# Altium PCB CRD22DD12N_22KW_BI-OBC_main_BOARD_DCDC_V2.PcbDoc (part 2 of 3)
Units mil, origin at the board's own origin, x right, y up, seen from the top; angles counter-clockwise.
Board outline 9308.07 x 7086.6 mil, 4 copper layers (TOP, GND02, POWER03, BOTTOM), stack 74.3 mil thick; 339 components, 177 nets, 874 pads, 199 vias.
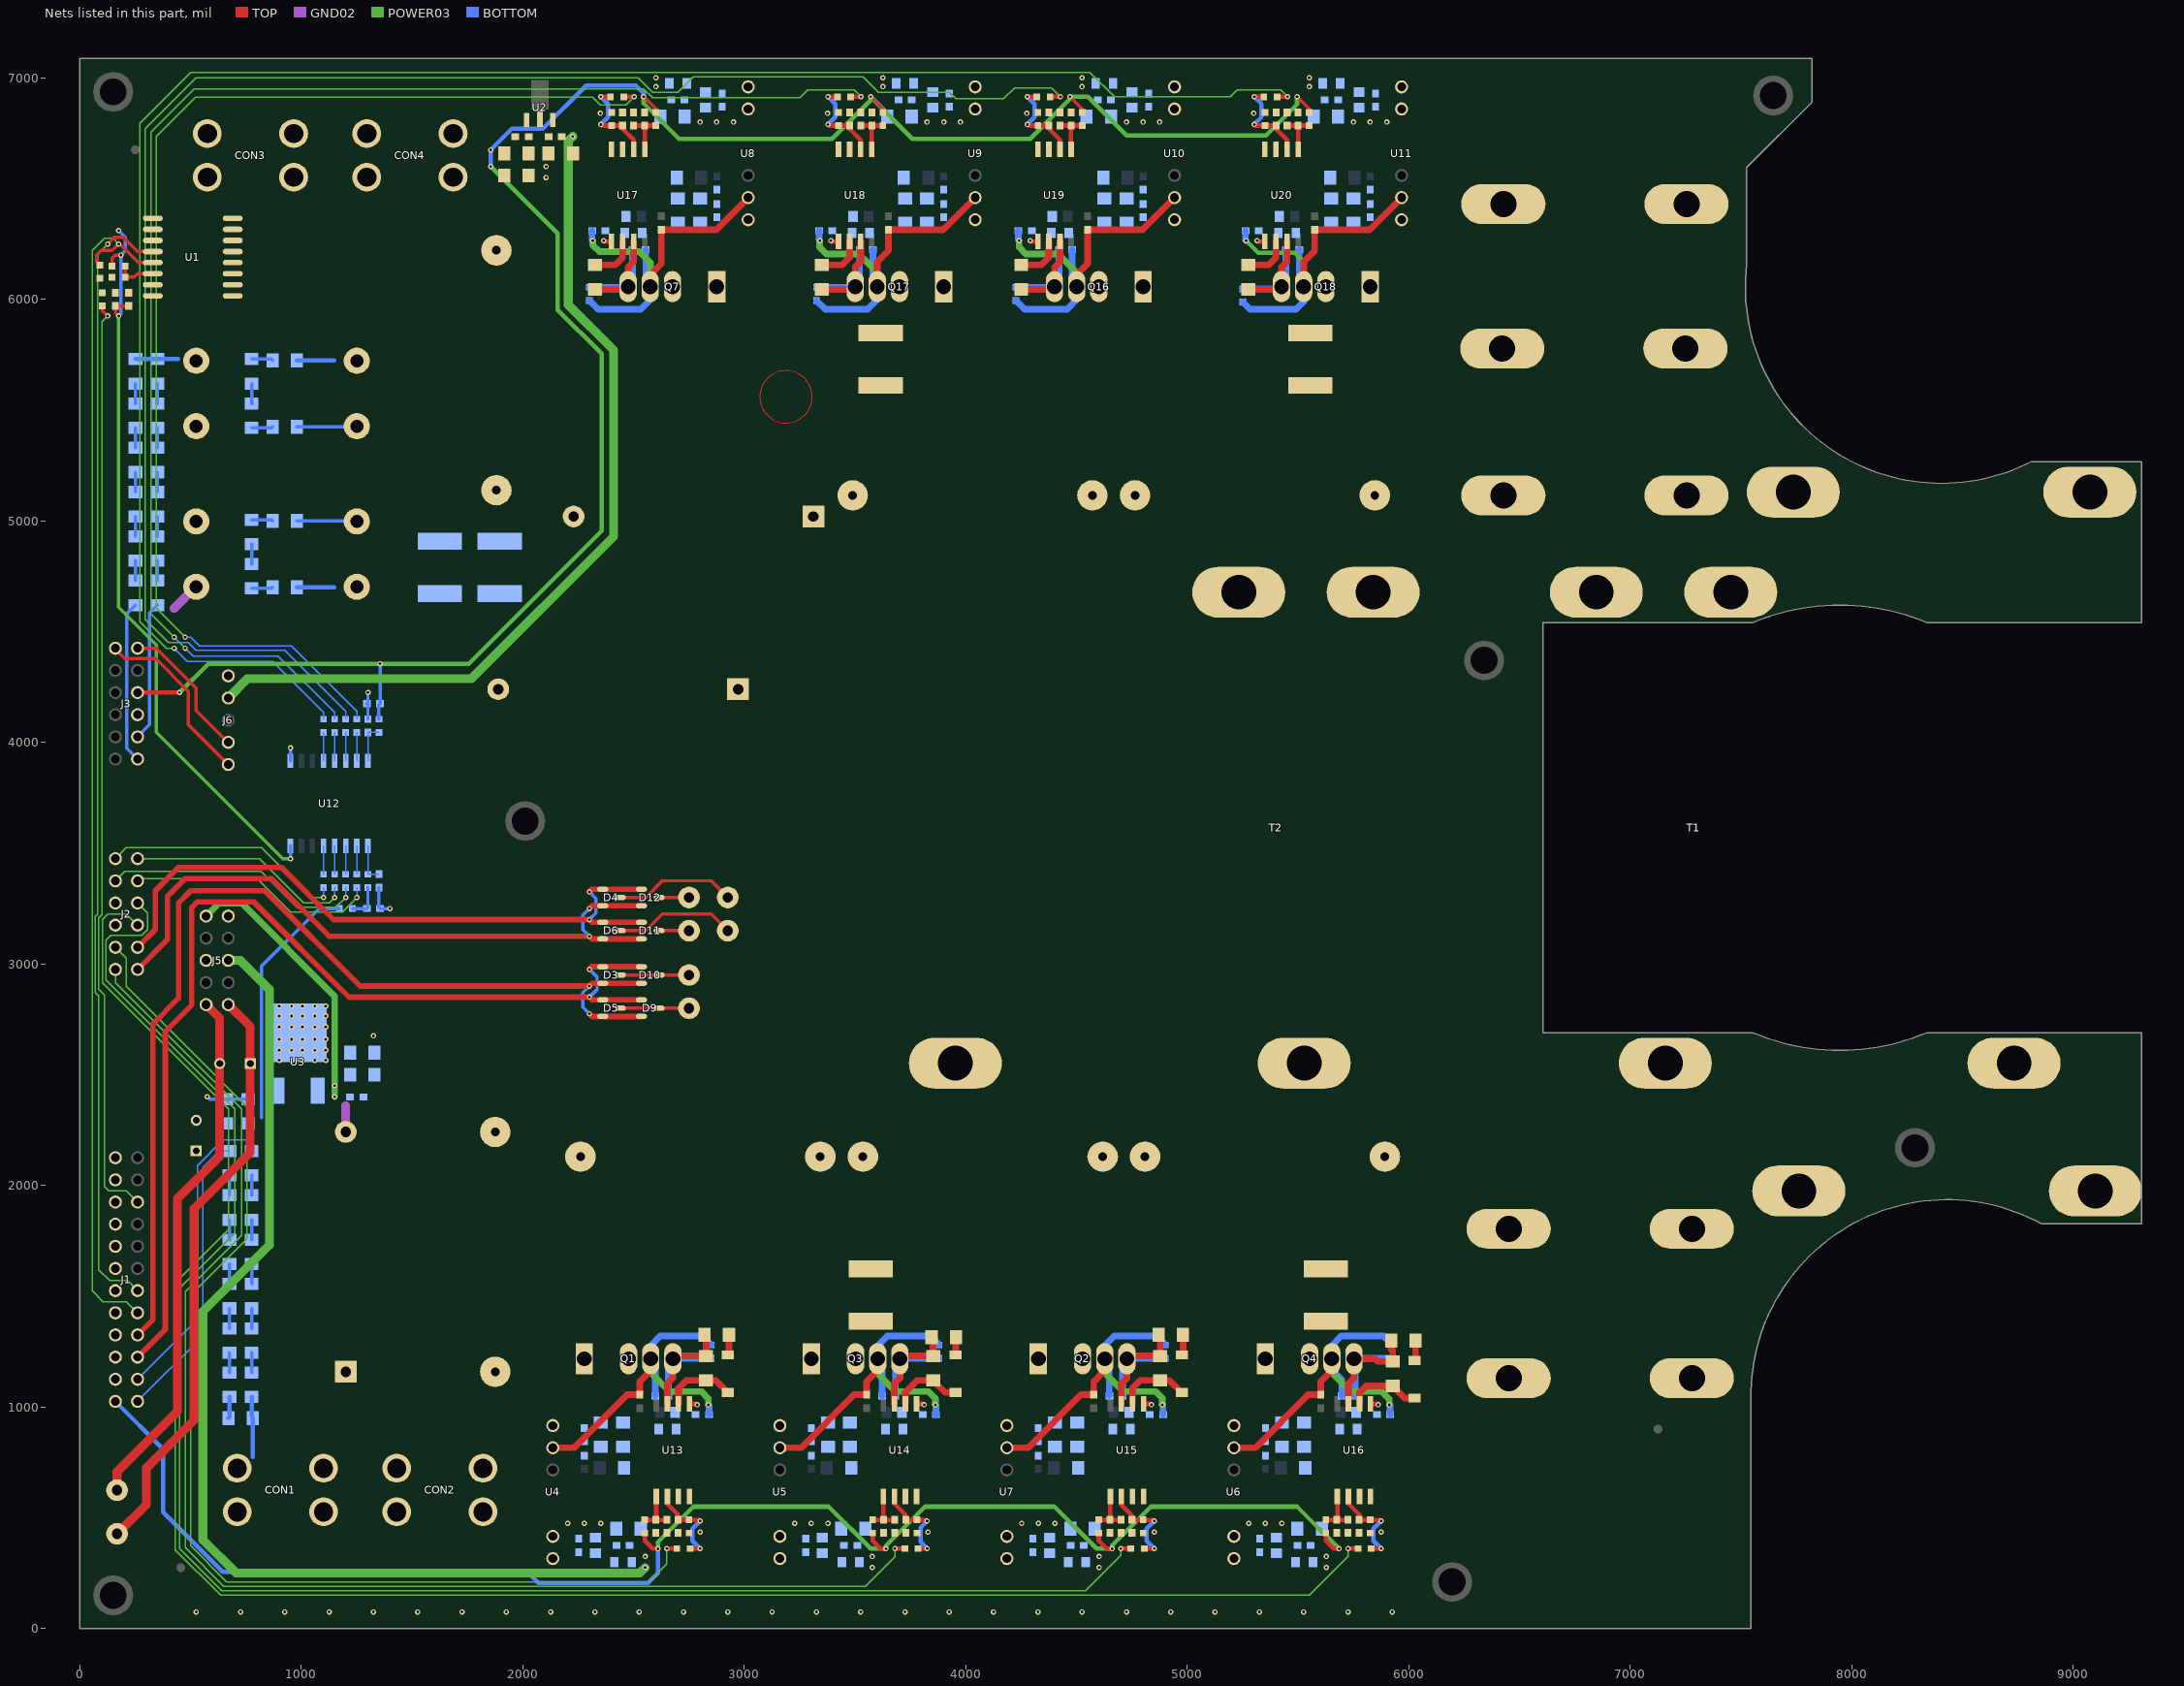
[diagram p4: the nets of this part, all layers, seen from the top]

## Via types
v1: diameter 24, hole 12, TOP to BOTTOM, tented both sides, 199 vias

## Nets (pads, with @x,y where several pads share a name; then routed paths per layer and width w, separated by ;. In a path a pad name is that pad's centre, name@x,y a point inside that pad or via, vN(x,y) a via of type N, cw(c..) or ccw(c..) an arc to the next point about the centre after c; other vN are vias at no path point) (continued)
AGND: C20.2 C21.2 C49.1 C50.1 C51.1 C52.1 C53.1 C54.2 C66.2 C67.2 C70.2 C71.2 C73.2 C74.2 C75.2 C76.2 C77.2 C78.2 C79.2 C80.2 C81.2 C82.2 C83.2 C84.2 C130.2 C131.1 C134.2 C135.2 C136.2 C141.2 C142.2 C143.2 C148.2 C149.2 C150.2 C155.2 C156.2 C157.2 J1.13 J1.15 J1.17 J1.19 J1.21 J2.6 J2.8 J5.6 J5.9 R45.2 R105.2 R110.2 R114.2 R117.2 U1.9 U1.10 U1.11 U3.2 U4.2 U5.2 U6.2 U7.2 U12.8 U13.3 U13.4 U14.3 U14.4 U15.3 U15.4 U16.3 U16.4 | length 3901.4
  TOP w15: R45.2@145.08,6150 145.08,6185.08 160,6200 v1(185,6200) ; v1(175,5925) 160,5940 C21.2@160,5970.08 C20.2@220,5970.08
  GND02 w40: 1200,2241.34 1200,2360
  POWER03 w15: v1(175,5925) 175,4610 345,4440 345,4045 915,3475 v1(950,3475)
  BOTTOM w15: v1(175,5925) 185,5935 v1(185,6200) 205,6220 205,6280 v1(175,6310) ; v1(575,2400) 585.63,2389.37 C53.1@659.25,2389.37 C52.1@759.25,2389.37 ; v1(950,3475) U12.8@950,3533 ; C131.1@1350,3345.08 1350,3254.92 C130.2@1354.92,3250 v1(1400,3250)
  other v1: 525,75 725,75 925,75 1125,75 1325,75 1525,75 1725,75 1925,75 2125,75 2325,75 2525,75 2725,75 2925,75 3125,75 3325,75 3525,75 3725,75 3925,75 4125,75 4325,75 4525,75 4725,75 4925,75 5125,75 5325,75 5525,75 5725,75 5925,75 2800,435.68 3829.17,435.68 4850,435.68 5875,435.68 2202,475 2277,475 2352,475 3227,475 3302,475 3377,475 4252,475 4327,475 4402,475 5277,475 5352,475 5427,475 900,2565 955,2565 1005,2565 1060,2565 1110,2565 900,2610 955,2610 1005,2610 1060,2610 1110,2610 900,2660 955,2660 1005,2660 1060,2660 1110,2660 1325,2675 900,2715 955,2715 1005,2715 1060,2715 1110,2715 900,2765 955,2765 1005,2765 1060,2765 1110,2765 900,2810 955,2810 1005,2810 1060,2810 1110,2810
CAN5V_GND: J3.11 J6.2 | length 644.2
  TOP w15: J3.11@260,4425 345,4425 525,4245 525,4144.77 J6.2@669.52,4000.24
CAN_5V: J3.12 J6.1 | length 817.8
  TOP w15: J3.12@160,4425 160,4420 202,4378 342,4378 490,4230 490,4079.76 J6.1@669.52,3900.24
CLAMPQA: C5.1 Q1.4 R2.1 R4.1 R8.2 U13.7 | length 817.1
  TOP w30: U13.7@2652,1014 2652,1105 2677,1130 Q1.4@2677,1217.72 2689.4,1230.12 R4.1@2827,1230.12 2827,1317.88 R2.1@2819.88,1325
  BOTTOM w30: C5.1@2656.92,1050 2656.92,1197.64 Q1.4@2677,1217.72 2679.36,1220.08 R8.2@2850,1220.08
CLAMPQB: C14.1 Q3.4 R15.1 R19.1 R21.2 U14.7 | length 811.2
  TOP w30: U14.7@3677,1014 3677,1105 3702,1130 Q3.4@3702,1217.72 3714.4,1230.12 R19.1@3852,1230.12 3852,1307.88 R15.1@3844.88,1315
  BOTTOM w30: C14.1@3681.92,1050 3681.92,1197.64 Q3.4@3702,1217.72 3704.36,1220.08 R21.2@3879.17,1220.08
CLAMPQC: C4.1 Q2.4 R1.2 R5.2 R9.2 U15.7 | length 817.1
  TOP w30: U15.7@4702,1014 4702,1105 4727,1130 Q2.4@4727,1217.72 4739.4,1230.12 R5.2@4877,1230.12 4877,1317.88 R1.2@4869.88,1325
  BOTTOM w30: C4.1@4706.92,1050 4706.92,1197.64 Q2.4@4727,1217.72 4729.36,1220.08 R9.2@4900,1220.08
CLAMPQD: C15.1 Q4.4 R14.2 R20.2 R22.2 U16.7 | length 835.9
  TOP w30: U16.7@5727,1014 5727,1105 5752,1130 Q4.4@5752,1217.72 5847.28,1217.72 5859.88,1205.12 R20.2@5927,1205.12 5927,1253 5919.88,1260.12 R14.2@5919.88,1300
  BOTTOM w30: C15.1@5756.92,1050 5756.92,1212.8 Q4.4@5752,1217.72 5754.36,1220.08 R22.2@5925,1220.08
CLAMPQSA: C22.1 Q7.4 R58.1 R62.2 U17.7 | length 721.2
  TOP w30: R58.1@2325,6044.88 2462.6,6044.88 Q7.4@2475,6057.28 2475,6145 2500,6170 U17.7@2500,6261
  BOTTOM w30: R62.2@2300,6054.92 2472.64,6054.92 Q7.4@2475,6057.28 2495.08,6077.36 C22.1@2495.08,6225
CLAMPQSB: C42.1 Q17.4 R72.1 R75.2 U18.7 | length 721.2
  TOP w30: R72.1@3350,6044.88 3487.6,6044.88 Q17.4@3500,6057.28 3500,6145 3525,6170 U18.7@3525,6261
  BOTTOM w30: R75.2@3325,6054.92 3497.64,6054.92 Q17.4@3500,6057.28 3520.08,6077.36 C42.1@3520.08,6225
CLAMPQSC: C23.1 Q16.4 R59.2 R64.2 U19.7 | length 721.2
  TOP w30: R59.2@4250,6044.88 4387.6,6044.88 Q16.4@4400,6057.28 4400,6145 4425,6170 U19.7@4425,6261
  BOTTOM w30: R64.2@4225,6054.92 4397.64,6054.92 Q16.4@4400,6057.28 4420.08,6077.36 C23.1@4420.08,6225
CLAMPQSD: C43.1 Q18.4 R73.2 R76.2 U20.7 | length 724.2
  TOP w30: R73.2@5275,6044.88 5412.6,6044.88 Q18.4@5425,6057.28 5425,6145 5450,6170 U20.7@5450,6261
  BOTTOM w30: R76.2@5250,6047.64 5415.35,6047.64 Q18.4@5425,6057.28 5445.08,6077.36 C43.1@5445.08,6225
CS: D4.2 D6.2 D11.2 D12.2 J2.1 | length 3062.4
  TOP w25: J2.1@260,2975 395,3110 395,3305 475,3385 865,3385 1125,3125 v1(2300,3125) 2312.4,3112.6 D6.2@2360.24,3112.6 D11.2@2535.24,3112.6 ; v1(2300,3250) 2312.6,3262.6 D4.2@2360.24,3262.6 D12.2@2535.24,3262.6
  BOTTOM w15: v1(2300,3125) 2270,3155 2270,3220 v1(2300,3250)
CS_PRI: D3.2 D5.2 D9.2 D10.2 J1.18 | length 4713.2
  TOP w25: J1.18@260,1325 330,1395 330,2730 445,2845 445,3275 500,3330 835,3330 1265,2900 v1(2300,2900) 2312.6,2912.6 D3.2@2360.24,2912.6 D10.2@2535.24,2912.6 ; v1(2300,2775) 2312.4,2762.6 D5.2@2360.24,2762.6 D9.2@2535.24,2762.6
  BOTTOM w15: v1(2300,2775) 2270,2805 2270,2870 v1(2300,2900)
CS_RTN: D4.1 D6.1 D11.1 D12.1 J2.3 | length 3019.7
  TOP w25: J2.3@260,3075 340,3155 340,3330 445,3435 910,3435 1145,3200 v1(2300,3200) 2312.6,3187.4 D6.1@2360.24,3187.4 D11.1@2535.24,3187.4 ; v1(2300,3325) 2312.4,3337.4 D4.1@2360.24,3337.4 D12.1@2535.24,3337.4
  BOTTOM w15: v1(2300,3200) 2330,3230 2330,3295 v1(2300,3325)
CS_RTN_PRI: D3.1 D5.1 D9.1 D10.1 J1.20 | length 4749.8
  TOP w25: J1.20@260,1225 385,1350 385,2695 505,2815 505,3255 530,3280 785,3280 1215,2850 v1(2300,2850) 2312.6,2837.4 D5.1@2360.24,2837.4 D9.1@2535.24,2837.4 ; v1(2300,2975) 2312.4,2987.4 D3.1@2360.24,2987.4 D10.1@2535.24,2987.4
  BOTTOM w15: v1(2300,2850) 2335,2885 2335,2940 v1(2300,2975)
DC-OV: J1.22 R70.1 | length 1410.6
  BOTTOM w6: J1.22@260,1125 530.25,1395.25 530.25,2090.25 645,2205 760,2205 775,2190 R70.1@775,2155.12
DC_14V_INPUT: C55.1 J4.2 J5.1 | length 2679
  TOP w40: J4.2@167.72,427.36 300.16,559.8 300.16,725.16 515,940 515,1895 768.9,2148.9 C55.1@768.9,2550 768.9,2716.76 J5.1@669.52,2816.14
DC_FB: J1.24 R69.1 | length 1328.3
  BOTTOM w6: J1.24@260,1025 555,1320 555,2080 630.12,2155.12 R69.1@675,2155.12
DCINPUT: C1.1 C2.1 C7.1 C8.1 C10.1 C185.1 C633.1 CON1.1 CON1.2 CON1.3 CON1.4 Q1.1 Q2.1 R34.2 R42.2 | length 272.1
  BOTTOM w6: 780,775 780.12,775.12
  BOTTOM w20: R42.2@775,1044.88 775,955.12 R34.2@780.12,950 780.12,775.12
DCPWM1A_1H: J2.4 R104.1 | length 5420.6
  TOP w20: v1(2650,360.68) R104.1@2695.08,360.68
  POWER03 w6: J2.4@160,3075 210,3025 210,2900 755,2355 755,1760 500,1505 500,372.78 662.78,210 2570,210 2650,290 v1(2650,360.68)
DCPWM1A_1L: J2.2 R108.1 | length 6364.2
  TOP w20: v1(3679.17,360.68) R108.1@3724.25,360.68
  POWER03 w6: J2.2@160,2975 160,2915 730,2345 730,1775 475,1520 475,365.91 649.91,191 3546,191 3679.17,324.17 v1(3679.17,360.68)
DCPWM2A_2H: J2.7 R112.1 | length 7908.9
  TOP w20: v1(4700,360.68) R112.1@4745.08,360.68
  POWER03 w6: J2.7@260,3275 305,3230 305,3155 280,3130 140,3130 117.5,3107.5 117.5,2927.5 700,2345 700,1785 450,1535 450,360 640,170 4540,170 4700,330 v1(4700,360.68)
DCPWM2A_2L: J2.5 R116.1 | length 8903.9
  TOP w20: v1(5725,360.68) R116.1@5770.08,360.68
  POWER03 w6: J2.5@260,3175 210,3225 125,3225 101,3201 101,2914 670,2345 670,1800 430,1560 430,355 635,150 5550,150 5725,325 v1(5725,360.68)
DRVA: D1.2 R4.2 U13.6 | length 331
  TOP w30: U13.6@2702,1014 2702,1085 2736.88,1119.88 R4.2@2827,1119.88 2870.47,1119.88 D1.2@2925,1065.35
DRVA_G: C5.2 C56.2 C57.2 C58.2 C85.1 C86.1 C138.2 C139.1 Q1.3 R8.1 U4.6 | length 1663.8
  TOP w30: U4.6@2135.07,815.75 2230.75,815.75 2469.92,1054.92 C139.1@2527,1054.92 2527,1115 2577,1165 Q1.3@2577,1217.72
  POWER03 w30: Q1.3@2577,1217.72 2577,1153 2660,1070 2805,1070 2837,1038 v1(2837,1010)
  BOTTOM w30: C5.2@2597.08,1050 2597.08,1197.64 Q1.3@2577,1217.72 2577,1277 2620,1320 2809.92,1320 R8.1@2850,1279.92 ; v1(2837,1010) 2839.92,1007.08 C138.2@2839.92,965
DRVB: D7.2 R19.2 U14.6 | length 324.7
  TOP w30: U14.6@3727,1014 3727,1067 3779.88,1119.88 R19.2@3852,1119.88 3906.53,1065.35 D7.2@3954.17,1065.35
DRVB_G: C14.2 C59.2 C60.2 C68.2 C89.1 C91.1 C144.2 C146.1 Q3.3 R21.1 U5.6 | length 1670.4
  TOP w30: U5.6@3160.07,815.75 3255.75,815.75 3494.92,1054.92 C146.1@3552,1054.92 3552,1115 3602,1165 Q3.3@3602,1217.72
  POWER03 w30: Q3.3@3602,1217.72 3602,1148.83 3680.83,1070 3830,1070 3862,1038 v1(3862,1010)
  BOTTOM w30: C14.2@3622.08,1050 3622.08,1197.64 Q3.3@3602,1217.72 3602,1277 3645,1320 3839.09,1320 R21.1@3879.17,1279.92 ; v1(3862,1010) 3864.92,1007.08 C144.2@3864.92,965
DRVC: D2.2 R5.1 U15.6 | length 331
  TOP w30: U15.6@4752,1014 4752,1085 4786.88,1119.88 R5.1@4877,1119.88 4920.47,1119.88 D2.2@4975,1065.35
DRVC_G: C4.2 C61.2 C62.2 C69.2 C87.1 C88.1 C152.2 C153.1 Q2.3 R9.1 U7.6 | length 1665
  TOP w30: U7.6@4185.07,815.75 4280.75,815.75 4519.92,1054.92 C153.1@4577,1054.92 4577,1115 4627,1165 Q2.3@4627,1217.72
  POWER03 w30: Q2.3@4627,1217.72 4627,1153 4710,1070 4857,1070 4887,1040 v1(4887,1010)
  BOTTOM w30: C4.2@4647.08,1050 4647.08,1197.64 Q2.3@4627,1217.72 4627,1277 4670,1320 4859.92,1320 R9.1@4900,1279.92 ; v1(4887,1010) 4889.92,1007.08 C152.2@4889.92,965
DRVD: D8.2 R20.1 U16.6 | length 333.9
  TOP w30: U16.6@5777,1014 5777,1064.88 5807,1094.88 R20.1@5927,1094.88 5981.53,1040.35 D8.2@6025,1040.35
DRVD_G: C15.2 C64.2 C65.2 C72.2 C90.1 C92.1 C158.2 C160.1 Q4.3 R22.1 U6.6 | length 1671.2
  TOP w30: U6.6@5210.07,815.75 5305.75,815.75 5544.92,1054.92 C160.1@5602,1054.92 5602,1115 5652,1165 Q4.3@5652,1217.72
  POWER03 w30: Q4.3@5652,1217.72 5652,1153 5735,1070 5875,1070 5912,1033 v1(5912,1010)
  BOTTOM w30: C15.2@5697.08,1050 5697.08,1122.92 5652,1168 Q4.3@5652,1217.72 5652,1277 5695,1320 5884.92,1320 R22.1@5925,1279.92 ; v1(5912,1010) 5914.92,1007.08 C158.2@5914.92,965
DRVSA: R58.2 U17.6 | length 210.4
  TOP w30: R58.2@2325,6155.12 2415.12,6155.12 2450,6190 U17.6@2450,6261
DRVSB: R72.2 U18.6 | length 210.4
  TOP w30: R72.2@3350,6155.12 3440.12,6155.12 3475,6190 U18.6@3475,6261
DRVSC: R59.1 U19.6 | length 210.4
  TOP w30: R59.1@4250,6155.12 4340.12,6155.12 4375,6190 U19.6@4375,6261
DRVSD: R73.1 U20.6 | length 210.4
  TOP w30: R73.1@5275,6155.12 5365.12,6155.12 5400,6190 U20.6@5400,6261
IGND: C55.2 J4.1 J5.2 | length 2409.4
  TOP w40: J4.1@167.72,624.22 167.72,707.72 440,980 440,1940 631.1,2131.1 C55.2@631.1,2550 631.1,2754.57 J5.2@569.52,2816.14
IOUT_ADC: J1.14 U1.12 | length 5117.2
  TOP w15: v1(125,6250) 155,6280 195,6280 259.25,6215.75 U1.12@329.01,6215.75
  POWER03 w6: v1(125,6250) 80,6205 80,3225.26 69,3214.26 69,2871 85,2855 85,1620 135,1570 215,1570 J1.14@260,1525
LEGA: Q1.2 Q3.1 T2.1
LEGB: CR1.2 CR2.2 Q2.2 Q4.1
N16123922: CON3.1 CON3.2 CON3.3 CON3.4 U1.5 U1.6 U1.7 U1.8
N16148248: R63.2 R67.1 | length 97
  BOTTOM w15: R67.1@775,5730.12 864.76,5730.12 R63.2@869.88,5725
N16148534: R68.2 R71.1 | length 97
  BOTTOM w15: R68.2@775,5419.88 864.76,5419.88 R71.1@869.88,5425
N16148538: R67.2 R68.1 | length 89.8
  BOTTOM w15: R68.1@775,5530.12 R67.2@775,5619.88
N16148540: R74.2 R77.1 | length 97
  BOTTOM w15: R77.1@775,5005.12 864.76,5005.12 R74.2@869.88,5000
N16148544: R78.2 R79.1 | length 97
  BOTTOM w15: R78.2@775,4694.88 864.76,4694.88 R79.1@869.88,4700
N16148550: C25.2 C26.2 C39.1 C40.1 R71.2 R74.1 | length 541.7
  BOTTOM w15: R74.1@980.12,5000 1247.64,5000 C39.1@1250,4997.64 ; R71.2@980.12,5425 1247.64,5425 C25.2@1250,5427.36
N16320789: R77.2 R78.1 | length 89.8
  BOTTOM w15: R78.1@775,4805.12 R77.2@775,4894.88
N17266948: R37.2 R44.1 | length 89.8
  BOTTOM w15: R44.1@350,5530.12 R37.2@350,5619.88
N17266951: R44.2 R49.1 | length 89.8
  BOTTOM w15: R49.1@350,5330.12 R44.2@350,5419.88
N17453412: C109.1 C110.1 R89.1 U9.1
N17453587: C98.1 C103.1 R88.1 U8.1
N17454238: C73.1 C74.1 R84.1 U4.1
N17454469: C71.1 C75.1 R85.1 U5.1
N17785545: C134.1 C135.1 R103.2 U13.1 | length 206.9
  TOP w20: R103.2@2550,490.6 C135.1@2600,490.6 ; U13.1@2602,596.68 2602,492.6 C135.1@2600,490.6 ; C134.1@2650,490.6 C135.1@2600,490.6
N17785579: C136.1 R104.2 R105.1 U13.2 | length 427.1
  TOP w20: U13.2@2652,596.68 2652,563 2700,515 C136.1@2700,490.6 R105.1@2750,490.6 2795.08,490.6 v1(2800,485.68) ; R104.2@2754.92,360.68 v1(2800,360.68)
  BOTTOM w20: v1(2800,360.68) 2765,395.68 2765,450.68 v1(2800,485.68)
N17785699: C141.1 C142.1 R107.2 U14.1 | length 207
  TOP w20: R107.2@3579.17,490.6 C141.1@3629.17,490.6 ; U14.1@3627,596.68 3627,492.77 C141.1@3629.17,490.6 ; C142.1@3679.17,490.6 C141.1@3629.17,490.6
N17785727: C143.1 R108.2 R110.1 U14.2 | length 416.3
  TOP w20: U14.2@3677,596.68 3677,563 3725,515 3725,494.77 C143.1@3729.17,490.6 R110.1@3779.17,490.6 3820.08,490.6 v1(3825,485.68) ; R108.2@3784.09,360.68 v1(3825,360.68)
  BOTTOM w20: v1(3825,360.68) 3795,390.68 3795,455.68 v1(3825,485.68)
N17785767: C137.1 C138.1 R106.1 U13.5 | length 36.7
  TOP w20: U13.5@2752,1014 2783,1014 v1(2787,1010)
N17785926: C144.1 C145.1 R109.1 U14.5 | length 36.7
  TOP w20: U14.5@3777,1014 3808,1014 v1(3812,1010)
N17788175: C148.1 C149.1 R111.2 U15.1 | length 206.9
  TOP w20: R111.2@4600,490.6 C149.1@4650,490.6 ; U15.1@4652,596.68 4652,492.6 C149.1@4650,490.6 ; C148.1@4700,490.6 C149.1@4650,490.6
N17788213: C150.1 R112.2 R114.1 U15.2 | length 427.1
  TOP w20: U15.2@4702,596.68 4702,558 4750,510 C150.1@4750,490.6 R114.1@4800,490.6 4845.08,490.6 v1(4850,485.68) ; R112.2@4804.92,360.68 v1(4850,360.68)
  BOTTOM w20: v1(4850,360.68) 4815,395.68 4815,450.68 v1(4850,485.68)
N17788281: C155.1 C156.1 R115.2 U16.1 | length 206.9
  TOP w20: R115.2@5625,490.6 C156.1@5675,490.6 ; U16.1@5677,596.68 5677,492.6 C156.1@5675,490.6 ; C155.1@5725,490.6 C156.1@5675,490.6
N17788301: C157.1 R116.2 R117.1 U16.2 | length 427.1
  TOP w20: U16.2@5727,596.68 5727,563 5775,515 C157.1@5775,490.6 R117.1@5825,490.6 5870.08,490.6 v1(5875,485.68) ; R116.2@5829.92,360.68 v1(5875,360.68)
  BOTTOM w20: v1(5875,360.68) 5840,395.68 5840,450.68 v1(5875,485.68)
N17788345: C151.1 C152.1 R113.1 U15.5 | length 36.7
  TOP w20: U15.5@4802,1014 4833,1014 v1(4837,1010)
N17788478: C158.1 C159.1 R118.1 U16.5 | length 36.7
  TOP w20: U16.5@5827,1014 5858,1014 v1(5862,1010)
N17790300: C161.1 C162.1 R119.2 U17.1 | length 206.1
  TOP w20: C161.1@2500,6784.4 C162.1@2550,6784.4 ; U17.1@2550,6678.32 C162.1@2550,6784.4 ; R119.2@2600,6784.4 C162.1@2550,6784.4
N17790352: C163.1 R120.2 R122.1 U17.2 | length 422.2
  TOP w20: v1(2352,6789.32) 2356.92,6784.4 R122.1@2400,6784.4 C163.1@2450,6784.4 2450,6769.32 2500,6719.32 U17.2@2500,6678.32 ; v1(2352,6914.32) R120.2@2395.08,6914.32
  BOTTOM w20: v1(2352,6789.32) 2385,6822.32 2385,6881.32 v1(2352,6914.32)
N17790406: C167.1 C168.1 R123.2 U18.1 | length 206.1
  TOP w20: C168.1@3525,6784.4 C167.1@3575,6784.4 ; U18.1@3575,6678.32 C167.1@3575,6784.4 ; R123.2@3625,6784.4 C167.1@3575,6784.4
N17790440: C169.1 R124.2 R125.1 U18.2 | length 422.2
  TOP w20: v1(3377,6789.32) 3381.92,6784.4 R125.1@3425,6784.4 C169.1@3475,6784.4 3475,6769.32 3525,6719.32 U18.2@3525,6678.32 ; v1(3377,6914.32) R124.2@3420.08,6914.32
  BOTTOM w20: v1(3377,6789.32) 3410,6822.32 3410,6881.32 v1(3377,6914.32)
N17790484: C164.1 C165.1 R121.1 U17.5 | length 36.7
  TOP w20: v1(2365,6265) 2369,6261 U17.5@2400,6261
N17790617: C170.1 C171.1 R126.1 U18.5 | length 36.7
  TOP w20: v1(3390,6265) 3394,6261 U18.5@3425,6261
N17792648: C173.1 C174.1 R127.2 U19.1 | length 206.1
  TOP w20: C174.1@4425,6784.4 C173.1@4475,6784.4 ; U19.1@4475,6678.32 C173.1@4475,6784.4 ; R127.2@4525,6784.4 C173.1@4475,6784.4
N17792696: C175.1 R128.2 R130.1 U19.2 | length 422.2
  TOP w20: v1(4277,6789.32) 4281.92,6784.4 R130.1@4325,6784.4 C175.1@4375,6784.4 4375,6769.32 4425,6719.32 U19.2@4425,6678.32 ; v1(4277,6914.32) R128.2@4320.08,6914.32
  BOTTOM w20: v1(4277,6789.32) 4310,6822.32 4310,6881.32 v1(4277,6914.32)
N17792742: C179.1 C180.1 R131.2 U20.1 | length 206.1
  TOP w20: C179.1@5450,6784.4 C180.1@5500,6784.4 ; U20.1@5500,6678.32 C180.1@5500,6784.4 ; R131.2@5550,6784.4 C180.1@5500,6784.4
N17792776: C181.1 R132.2 R133.1 U20.2 | length 422.2
  TOP w20: v1(5302,6789.32) 5306.92,6784.4 R133.1@5350,6784.4 C181.1@5400,6784.4 5400,6769.32 5450,6719.32 U20.2@5450,6678.32 ; v1(5302,6914.32) R132.2@5345.08,6914.32
  BOTTOM w20: v1(5302,6789.32) 5335,6822.32 5335,6881.32 v1(5302,6914.32)
N17792812: C176.1 C177.1 R129.1 U19.5 | length 36.7
  TOP w20: v1(4290,6265) 4294,6261 U19.5@4325,6261
N17792937: C182.1 C183.1 R134.1 U20.5 | length 36.7
  TOP w20: v1(5315,6265) 5319,6261 U20.5@5350,6261
N17820985: R36.2 R43.1 | length 89.8
  BOTTOM w15: R43.1@250,5530.12 R36.2@250,5619.88
N17820987: R43.2 R48.1 | length 89.8
  BOTTOM w15: R48.1@250,5330.12 R43.2@250,5419.88
N17935390: R52.2 R56.1 | length 89.8
  BOTTOM w15: R56.1@250,4930.12 R52.2@250,5019.88
N17935392: R56.2 R65.1 | length 89.8
  BOTTOM w15: R65.1@250,4730.12 R56.2@250,4819.88
N17935418: R53.2 R57.1 | length 89.8
  BOTTOM w15: R57.1@350,4930.12 R53.2@350,5019.88
N17935420: R57.2 R66.1 | length 89.8
  BOTTOM w15: R66.1@350,4730.12 R57.2@350,4819.88
N17935429: R49.2 R53.1 | length 89.8
  BOTTOM w15: R53.1@350,5130.12 R49.2@350,5219.88
N17935432: R48.2 R52.1 | length 89.8
  BOTTOM w15: R52.1@250,5130.12 R48.2@250,5219.88
N17962871: C78.1 C79.1 R86.1 U7.1
N17963706: C83.1 C84.1 R87.1 U6.1
N17964909: C115.1 C116.1 R90.1 U10.1
N17965565: C121.1 C122.1 R91.1 U11.1
N17977150: C131.2 R94.1 U12.1 | length 178.1
  BOTTOM w6: U12.1@1300,3533 R94.1@1300,3404.92 C131.2@1350,3404.92
N17977162: C130.1 R92.2 R94.2 | length 162.3
  BOTTOM w15: R92.2@1229.92,3250 C130.1@1295.08,3250 1300,3254.92 R94.2@1300,3345.08
N17977230: C132.2 R93.1 U12.16 | length 178.1
  BOTTOM w6: U12.16@1300,3917 C132.2@1300,4045.08 R93.1@1350,4045.08
N17977288: R95.1 U12.2 | length 128.1
  BOTTOM w6: R95.1@1250,3404.92 U12.2@1250,3533
N17977296: R97.1 U12.3 | length 128.1
  BOTTOM w6: R97.1@1200,3404.92 U12.3@1200,3533
N17977322: R99.1 U12.4 | length 128.1
  BOTTOM w6: R99.1@1150,3404.92 U12.4@1150,3533
N17977346: R101.1 U12.5 | length 128.1
  BOTTOM w6: R101.1@1100,3404.92 U12.5@1100,3533
N17977366: R96.1 U12.15 | length 128.1
  BOTTOM w6: U12.15@1250,3917 R96.1@1250,4045.08
N17977368: R98.1 U12.14 | length 128.1
  BOTTOM w6: U12.14@1200,3917 R98.1@1200,4045.08
N17977394: R100.1 U12.13 | length 128.1
  BOTTOM w6: U12.13@1150,3917 R100.1@1150,4045.08
N17977396: R102.1 U12.12 | length 128.1
  BOTTOM w6: U12.12@1100,3917 R102.1@1100,4045.08
N17988090: CR1.1 CR2.1 L2.3
N17988199: CR3.1 CR4.1 CR5.1 L1.1
N17988317: L1.3 T1.7 T2.7
N17990244: R34.1 R41.2 | length 97
  BOTTOM w20: R34.1@669.88,950 675,955.12 R41.2@675,1044.88
N17990246: R41.1 R46.2 | length 89.8
  BOTTOM w15: R41.1@675,1155.12 R46.2@675,1244.88
N17990248: R46.1 R50.2 | length 89.8
  BOTTOM w15: R46.1@675,1355.12 R50.2@675,1444.88
N17990300: R54.1 R60.2 | length 89.8
  BOTTOM w15: R54.1@675,1755.12 R60.2@675,1844.88
N17990318: R60.1 R69.2 | length 89.8
  BOTTOM w15: R60.1@675,1955.12 R69.2@675,2044.88
N17990348: R50.1 R54.2 | length 89.8
  BOTTOM w15: R50.1@675,1555.12 R54.2@675,1644.88
N17997979: C20.1 C21.1 R38.2 R39.1 R40.1 U1.15 U1.16
N17998079: R39.2 R45.1 U1.14 | length 180.6
  TOP w15: R45.1@204.92,6150 R39.2@204.92,6100 245,6100 260.75,6115.75 U1.14@329.01,6115.75
N18014670: R42.1 R47.2 | length 89.8
  BOTTOM w15: R42.1@775,1155.12 R47.2@775,1244.88
N18014680: R47.1 R51.2 | length 89.8
  BOTTOM w15: R47.1@775,1355.12 R51.2@775,1444.88
N18014712: R55.1 R61.2 | length 89.8
  BOTTOM w15: R55.1@775,1755.12 R61.2@775,1844.88
N18014714: R61.1 R70.2 | length 89.8
  BOTTOM w15: R61.1@775,1955.12 R70.2@775,2044.88
N18014716: R51.1 R55.2 | length 89.8
  BOTTOM w15: R51.1@775,1555.12 R55.2@775,1644.88
N18067595: L2.1 T1.4
N18080140: D1.1 R2.2 | length 92.5
  TOP w30: D1.1@2925,1234.65 2930.12,1239.77 R2.2@2930.12,1325
N18080143: D2.1 R1.1 | length 92.5
  TOP w30: D2.1@4975,1234.65 4980.12,1239.77 R1.1@4980.12,1325
N18080178: D7.1 R15.2 | length 80.7
  TOP w30: D7.1@3954.17,1234.65 3954.17,1314.05 R15.2@3955.12,1315
N18080222: D8.1 R14.1 | length 92.5
  TOP w30: D8.1@6025,1209.65 6030.12,1214.77 R14.1@6030.12,1300
N18096975: CT5.1 D5.3 D9.3 | length 310.2
  TOP w15: D5.3@2439.76,2800 D9.3@2614.76,2800 CT5.1@2750,2800
N18096977: CT1.1 D3.3 D10.3 | length 310.2
  TOP w15: D3.3@2439.76,2950 D10.3@2614.76,2950 CT1.1@2750,2950
N18097182: CT8.1 D6.3 | length 547.4
  TOP w15: D6.3@2439.76,3150 2555,3150 2630,3225 2850,3225 CT8.1@2925,3150
N18097184: CT7.1 D4.3 | length 547.4
  TOP w15: D4.3@2439.76,3300 2555,3300 2630,3375 2850,3375 CT7.1@2925,3300
N18126472: T1.1 T2.4
N18143894: CT2.1 D12.3 | length 135.2
  TOP w15: D12.3@2614.76,3300 CT2.1@2750,3300
N18143920: CT6.1 D11.3 | length 135.2
  TOP w15: D11.3@2614.76,3150 CT6.1@2750,3150
OUTPUT_OC: J1.16 R40.2 U1.13 | length 5455.5
  TOP w15: R40.2@90,6154.92 75,6169.92 75,6200 95.5,6220.5 145.5,6220.5 v1(175,6250) 180,6250 264.25,6165.75 U1.13@329.01,6165.75
  POWER03 w6: v1(175,6250) 150,6275 110,6275 55,6220 55,1525 105,1475 210,1475 J1.16@260,1425
P6.5V: C49.2 C50.2 C51.2 J5.10 U3.3 | length 1233.8
  POWER03 w30: J5.10@569.52,3216.14 628.38,3275 730,3275 1150,2855 v1(1150,2450) v1(1150,2400)
PGND: C1.2 C2.2 C7.2 C8.2 C10.2 C185.2 C633.2 CON2.1 CON2.2 CON2.3 CON2.4 Q3.2 Q4.2
PWM1A: J1.1
PWM1B: J1.3
PWM1C: J1.5
PWM1D: J1.7
PWM1E: J1.9
PWM1F: J1.11
SGND: C44.1 C45.1 C46.1 C47.1 C48.1 C96.2 C98.2 C101.2 C103.2 C108.2 C109.2 C110.2 C111.2 C112.2 C115.2 C116.2 C118.2 C119.2 C120.2 C121.2 C122.2 C129.2 C132.1 C161.2 C162.2 C163.2 C167.2 C168.2 C169.2 C173.2 C174.2 C175.2 C179.2 C180.2 C181.2 J3.5 J6.5 R122.2 R125.2 R130.2 R133.2 U2.2 U8.2 U9.2 U10.2 U11.2 U12.9 U17.3 U17.4 U18.3 U18.4 U19.3 U19.4 U20.3 U20.4 | length 319.8
  GND02 w40: 425,4605 522.36,4702.36
  BOTTOM w15: U12.9@950,3917 v1(950,3975) ; C132.1@1300,4104.92 1300,4170.08 C129.2@1295.08,4175 1300,4179.92 v1(1300,4225)
  other v1: 2105,6550 2105,6600 2800,6800 2875,6800 2950,6800 3825,6800 3900,6800 3975,6800 4725,6800 4800,6800 4875,6800 5750,6800 5825,6800 5900,6800 2350,6839.32 3375,6839.32 4275,6839.32 5300,6839.32
SLEGA: CR3.2 CR4.2 CR5.2 Q7.2 Q17.1
SLEGB: Q16.2 Q18.1 T1.8 T2.8
SPGND: C27.2 C28.2 C32.2 C33.2 C34.2 C35.2 C36.2 C37.2 C39.2 C40.2 C186.2 CON4.1 CON4.2 CON4.3 CON4.4 Q17.2 Q18.2 R79.2 | length 172.5
  GND02 w6: C40.2@522.36,4702.36 C40.2@525,4702.36 C40.2@525,4700
  BOTTOM w20: R79.2@980.12,4700 1147.64,4700
SR-PWM-A: J2.9 R95.2 | length 1128.3
  POWER03 w6: J2.9@260,3375 270,3385 800,3385 950,3235 1185,3235 v1(1250,3300)
  BOTTOM w6: v1(1250,3300) R95.2@1250,3345.08
SR-PWM-A-S: R96.2 R120.1 | length 5569.6
  TOP w6: R120.1@2454.92,6914.32 R120.1@2456.92,6914.32
  TOP w20: R120.1@2456.92,6914.32 v1(2502,6914.32)
  POWER03 w6: v1(475,4475) 345,4605 345,6735 523,6913 2314,6913 2348.5,6878.5 2466.18,6878.5 v1(2502,6914.32)
  BOTTOM w6: v1(475,4475) 500,4475 540,4435 955,4435 1250,4140 R96.2@1250,4104.92
SR-PWM-B: J2.10 R97.2 | length 1188.6
  POWER03 w6: J2.10@160,3375 202.5,3417.5 817.5,3417.5 980,3255 1155,3255 v1(1200,3300)
  BOTTOM w6: v1(1200,3300) R97.2@1200,3345.08
SR-PWM-B-S: R98.2 R124.1 | length 6651
  TOP w20: R124.1@3479.92,6914.32 v1(3527,6914.32)
  POWER03 w6: v1(425,4475) 320,4580 320,6755 515,6950 2545,6950 2585,6910 3250,6910 3285,6945 3496.32,6945 v1(3527,6914.32)
  BOTTOM w6: v1(425,4475) 450,4450 490,4450 525,4415 925,4415 1200,4140 R98.2@1200,4104.92
SR-PWM-C: J2.11 R99.2 | length 1028.3
  POWER03 w6: J2.11@260,3475 810,3475 1010,3275 1125,3275 v1(1150,3300)
  BOTTOM w6: v1(1150,3300) R99.2@1150,3345.08
SR-PWM-C-S: R100.2 R128.1 | length 7683.3
  TOP w20: R128.1@4379.92,6914.32 v1(4427,6914.32)
  POWER03 w6: v1(475,4425) 450,4450 400,4450 295,4555 295,6770 525,7000 2520,7000 2585,6935 2700,6935 2770,7005 3535,7005 3605.01,6934.99 3925.01,6934.99 3955,6905 4170,6905 4220,6955 4386.32,6955 v1(4427,6914.32)
  BOTTOM w6: v1(475,4425) 510,4390 895,4390 1150,4135 R100.2@1150,4104.92
SR-PWM-D: J2.12 R101.2 | length 1099
  POWER03 w6: J2.12@160,3475 210,3525 820,3525 1045,3300 v1(1100,3300)
  BOTTOM w6: v1(1100,3300) R101.2@1100,3345.08
SR-PWM-D-S: R102.2 R132.1 | length 8675.5
  TOP w20: R132.1@5404.92,6914.32 v1(5452,6914.32)
  POWER03 w6: v1(425,4425) 390,4425 270,4545 270,6795 500,7025 4560,7025 4670.68,6914.32 5194.32,6914.32 5225,6945 5421.32,6945 v1(5452,6914.32)
  BOTTOM w6: v1(425,4425) 485,4365 870,4365 1100,4135 R102.2@1100,4104.92
SRA_G: C22.2 C93.2 C94.2 C95.2 C113.1 C114.1 C165.2 C166.1 Q7.3 R62.1 U8.6 | length 1741.7
  TOP w30: Q7.3@2575,6057.28 2575,6110 2625,6160 2625,6220.08 C166.1@2625,6314.74 2872.42,6314.74 U8.6@3016.93,6459.25
  POWER03 w30: v1(2315,6265) 2315,6245 2345,6215 2525,6215 2575,6165 Q7.3@2575,6057.28
  BOTTOM w30: R62.1@2300,5995.08 2340.08,5955 2532,5955 2575,5998 Q7.3@2575,6057.28 2554.92,6077.36 C22.2@2554.92,6225 ; C165.2@2312.08,6310 2312.08,6267.92 v1(2315,6265)
SRB_G: C42.2 C97.2 C99.2 C102.2 C123.1 C124.1 C170.2 C172.1 Q17.3 R75.1 U9.6 | length 1722.4
  TOP w30: Q17.3@3600,6057.28 3600,6170.08 3650,6220.08 C172.1@3650,6314.74 3897.42,6314.74 U9.6@4041.93,6459.25
  POWER03 w30: v1(3340,6265) 3340,6235 3370,6205 3517,6205 3600,6122 Q17.3@3600,6057.28
  BOTTOM w30: R75.1@3325,5995.08 3365.08,5955 3557,5955 3600,5998 Q17.3@3600,6057.28 3579.92,6077.36 C42.2@3579.92,6225 ; C170.2@3337.08,6310 3337.08,6267.92 v1(3340,6265)
SRC_G: C23.2 C100.2 C104.2 C105.2 C125.1 C126.1 C177.2 C178.1 Q16.3 R64.1 U10.6 | length 1722.4
  TOP w30: Q16.3@4500,6057.28 4500,6110 4550,6160 4550,6220.08 C178.1@4550,6314.74 4797.42,6314.74 U10.6@4941.93,6459.25
  POWER03 w30: v1(4240,6265) 4240,6235 4270,6205 4417,6205 4500,6122 Q16.3@4500,6057.28
  BOTTOM w30: R64.1@4225,5995.08 4265.08,5955 4457,5955 4500,5998 Q16.3@4500,6057.28 4479.92,6077.36 C23.2@4479.92,6225 ; C177.2@4237.08,6310 4237.08,6267.92 v1(4240,6265)
SRD_G: C43.2 C106.2 C107.2 C117.2 C127.1 C128.1 C182.2 C184.1 Q18.3 R76.1 U11.6 | length 1734.6
  TOP w30: Q18.3@5525,6057.28 5525,6170.08 5575,6220.08 C184.1@5575,6314.74 5822.42,6314.74 U11.6@5966.93,6459.25
  POWER03 w20: v1(5265,6265) 5320,6210 5485,6210 5525,6170 Q18.3@5525,6057.28
  BOTTOM w30: R76.1@5250,5987.8 5282.8,5955 5490,5955 5525,5990 Q18.3@5525,6057.28 5504.92,6077.36 C43.2@5504.92,6225 ; C182.2@5262.08,6310 5262.08,6267.92 v1(5265,6265)
VO1+: J3.1 R65.2 | length 731.3
  BOTTOM w15: R65.2@250,4619.88 211,4580.88 211,3974 J3.1@260,3925
VO2+: J3.3 R66.2 | length 632.2
  BOTTOM w15: J3.3@260,4025 315,4080 315,4584.88 R66.2@350,4619.88
VO+: C25.1 C26.1 C27.1 C28.1 C32.1 C33.1 C34.1 C35.1 C36.1 C37.1 C186.1 Q7.1 Q16.1 R36.1 R37.1 R63.1 U1.1 U1.2 U1.3 U1.4 | length 1101.5
  TOP w2: 3305.5,5560 ccw(c3187.5,5560) 3305.5,5560
  BOTTOM w20: R36.1@250,5730.12 R37.1@350,5730.12 442.52,5730.12 ; R63.1@980.12,5725 1147.64,5725
VP3.3D: J1.6 R38.1 | length 4191.4
  TOP w15: R38.1@100,5970.08 100,5950 v1(125,5925)
  POWER03 w6: v1(125,5925) 100,5900 100,3222.63 85,3207.63 85,2885 110,2860 110,1995 130,1975 210,1975 J1.6@260,1925
VP+5V: C52.2 C53.2 C54.1 J1.23 R92.1 R103.1 R107.1 R111.1 R115.1 U3.1 | length 8250.9
  TOP w20: R103.1@2550,430.76 2550,395 2585,360 v1(2610,360) ; R107.1@3579.17,430.76 3579.17,395 3614.17,360 v1(3639.17,360) ; R111.1@4600,430.76 4600,395 4635,360 v1(4660,360) ; R115.1@5625,430.76 5625,395 5660,360 v1(5685,360)
  POWER03 w20: v1(2610,360) 2610,390 2770,550 3380,550 3570,360 v1(3639.17,360) 3639.17,374.17 3815,550 4400,550 4590,360 v1(4660,360) 4660,375 4835,550 5495,550 v1(5685,360)
  BOTTOM w15: 820,2305 820,2990 1080,3250 R92.1@1170.08,3250
  BOTTOM w20: J1.23@160,1025 375,810 375,525 645,255 2020,255 2070,205 2565,205 2610,250 v1(2610,360)
VP+15V: C66.1 C67.1 C70.1 C76.1 C77.1 C80.1 C81.1 C82.1 J5.5 R84.2 R85.2 R86.2 R87.2 | length 4918.5
  POWER03 w40: J5.5@669.52,3016.14 723.86,3016.14 855,2885 855,1730 555,1430 555,400 705,250 2527,250 v1(2552,275)
  other v1: 3577,275 4602,275 5627,275 2552,325 3577,325 4602,325 5627,325
VP+15V_DCDCA: C56.1 C57.1 C58.1 R106.2 U4.7
VP+15V_DCDCB: C59.1 C60.1 C68.1 R109.2 U5.7
VP+15V_DCDCC: C61.1 C62.1 C69.1 R113.2 U7.7
VP+15V_DCDCD: C64.1 C65.1 C72.1 R118.2 U6.7
VS+5V: C46.2 C47.2 C48.2 C129.1 J3.7 R93.2 R119.1 R123.1 R127.1 R131.1 U2.1 | length 9247.6
  TOP w15: v1(2545,6914.32) 2600,6859.32 R119.1@2600,6844.24 ; v1(3570,6914.32) 3625,6859.32 R123.1@3625,6844.24 ; v1(4470,6914.32) 4525,6859.32 R127.1@4525,6844.24 ; v1(5495,6914.32) 5550,6859.32 R131.1@5550,6844.24
  TOP w20: J3.7@260,4225 v1(450,4225)
  POWER03 w20: v1(450,4225) 580,4355 v1(1354.92,4355) 1755,4355 2355,4955 2355,5755 2157.48,5952.52 2157.48,6297.52 v1(1855,6600) ; v1(2545,6914.32) 2545,6885 2705,6725 3395,6725 3570,6900 v1(3570,6914.32) 3759.32,6725 4290,6725 4470,6905 v1(4470,6914.32) 4550.68,6914.32 4725,6740 5355,6740 5495,6880 v1(5495,6914.32)
  BOTTOM w15: R93.2@1350,4104.92 1350,4170.08 C129.1@1354.92,4175 v1(1354.92,4355)
  BOTTOM w20: v1(1855,6600) v1(1855,6675) 1950,6770 2090,6770 2285,6965 2510,6965 2545,6930 v1(2545,6914.32)
VS+15V: C44.2 C45.2 C96.1 C101.1 C108.1 C111.1 C112.1 C118.1 C119.1 C120.1 J6.4 R88.2 R89.2 R90.2 R91.2 U2.3 | length 3940.9
  POWER03 w40: J6.4@669.52,4200.24 756.8,4287.51 1767.51,4287.51 2410,4930 2410,5770 2205,5975 2205,6715 v1(2225,6735)
  other v1: 2600,6960 3625,6960 4525,6960 5550,6960 2600,7000 3625,7000 4525,7000 5550,7000
VS+15V_DCDCA: C93.1 C94.1 C95.1 R121.2 U8.7
VS+15V_DCDCB: C97.1 C99.1 C102.1 R126.2 U9.7
VS+15V_DCDCC: C100.1 C104.1 C105.1 R129.2 U10.7
VS+15V_DCDCD: C106.1 C107.1 C117.1 R134.2 U11.7
pads on no net: J1.2 J1.4 J1.8 J1.10 J1.12 J3.2 J3.4 J3.6 J3.8 J3.9 J3.10 J5.3 J5.4 J5.7 J5.8 J6.3 U2. U12.6 U12.7 U12.10 U12.11
copper on no net: | length 2218.2
  TOP w12: 195,6650 225,6620 275,6620 305,6650 305,6700 275,6730 225,6730 195,6700 195,6650 ; 400,250 430,220 480,220 510,250 510,300 480,330 430,330 400,300 400,250 ; 7070,875 7100,845 7150,845 7180,875 7180,925 7150,955 7100,955 7070,925 7070,875
  BOTTOM w12: 195,6650 225,6620 275,6620 305,6650 305,6700 275,6730 225,6730 195,6700 195,6650 ; 400,250 430,220 480,220 510,250 510,300 480,330 430,330 400,300 400,250 ; 7070,875 7100,845 7150,845 7180,875 7180,925 7150,955 7100,955 7070,925 7070,875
